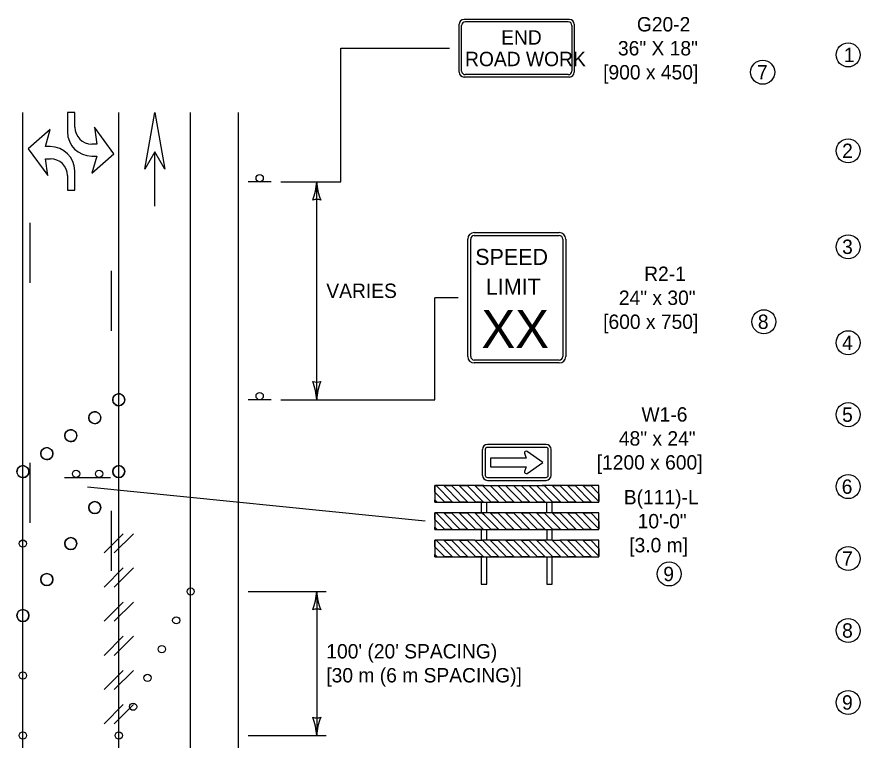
# Model space of a CAD drawing. Extents: x 49991.4 to 50021, y 49987.6 to 50011.4.
# Drawn here: x 50002.173 to 50005.691, y 50006.157 to 50009.172 of the extents above; entities that cross this region are included whole.
import ezdxf

# ---------------------------------------------------------------- set-up
doc = ezdxf.new("R2010")
doc.units = 0
for name, color, linetype in [('Level 1', 7, 'Continuous'), ('Level 2', 7, 'Continuous'), ('Level 3', 7, 'Continuous')]:
    doc.layers.add(name, color=color, linetype=linetype)

msp = doc.modelspace()

# ---------------------------------------------------------------- linework, layer by layer
at = {"layer": 'Level 1'}
for p, q in [((50004.4785, 50009.1613), (50004.0385, 50009.1613)), ((50004.0185, 50008.9413), (50004.0185, 50009.1413)), ((50004.0285, 50008.9463), (50004.0285, 50009.1363)), ((50004.4735, 50009.1513), (50004.0435, 50009.1513)), ((50004.4885, 50009.1363), (50004.4885, 50008.9463)), ((50004.4985, 50009.1413), (50004.4985, 50008.9413)), ((50004.4784, 50008.9212), (50004.0384, 50008.9212)), ((50004.4735, 50008.9313), (50004.0435, 50008.9313)), ((50002.1979, 50000.4631), (50002.1979, 50008.7736)), ((50002.4144, 50008.7735), (50002.3838, 50008.7735)), ((50002.3838, 50008.7735), (50002.3838, 50008.6926)), ((50002.4144, 50008.7128), (50002.4144, 50008.7735)), ((50002.5979, 50000.4631), (50002.5979, 50008.7736)), ((50002.8979, 50000.4631), (50002.8979, 50008.7736)), ((50003.0979, 50000.4631), (50003.0979, 50008.7736)), ((50002.3123, 50008.7022), (50002.2205, 50008.6213)), ((50002.2919, 50008.6314), (50002.3123, 50008.7022)), ((50002.5778, 50008.6017), (50002.4961, 50008.7128)), ((50002.4961, 50008.7128), (50002.5063, 50008.6421)), ((50002.3123, 50008.6314), (50002.2919, 50008.6314)), ((50002.4798, 50008.6471), (50002.4798, 50008.6471)), ((50002.5063, 50008.6421), (50002.4859, 50008.6421)), ((50002.2205, 50008.6213), (50002.3021, 50008.5101)), ((50002.4859, 50008.5208), (50002.5778, 50008.6017)), ((50002.4859, 50008.5916), (50002.5063, 50008.5916)), ((50002.5063, 50008.5916), (50002.4859, 50008.5208)), ((50002.7479, 50008.3835), (50002.7479, 50008.6094)), ((50002.7483, 50008.3835), (50002.7483, 50008.6094)), ((50002.3021, 50008.5101), (50002.2919, 50008.5809)), ((50002.2919, 50008.5809), (50002.3123, 50008.5809)), ((50002.3184, 50008.5758), (50002.3184, 50008.5758)), ((50002.4144, 50008.4495), (50002.4144, 50008.5304)), ((50002.3838, 50008.5101), (50002.3838, 50008.4495)), ((50003.2339, 50008.4843), (50003.1379, 50008.4843)), ((50002.3838, 50008.4495), (50002.4144, 50008.4495)), ((50002.2279, 50008.0631), (50002.2279, 50008.3131)), ((50004.0811, 50008.2729), (50004.4356, 50008.2729)), ((50004.0539, 50007.7562), (50004.0539, 50008.2458)), ((50004.0663, 50007.7562), (50004.0663, 50008.2458)), ((50004.0811, 50008.2605), (50004.4356, 50008.2605)), ((50004.2583, 50008.2711), (50004.2583, 50008.2711)), ((50004.4504, 50008.2458), (50004.4504, 50007.7562)), ((50004.4628, 50008.2458), (50004.4628, 50007.7562)), ((50002.5679, 50007.8631), (50002.5679, 50008.1131)), ((50004.4356, 50007.7414), (50004.0811, 50007.7414)), ((50004.4356, 50007.729), (50004.0811, 50007.729)), ((50003.2339, 50007.576), (50003.1379, 50007.576)), ((50004.1148, 50007.3687), (50004.1148, 50007.2604)), ((50004.1272, 50007.3687), (50004.1272, 50007.2604)), ((50004.3809, 50007.3897), (50004.1358, 50007.3897)), ((50004.3809, 50007.3773), (50004.1358, 50007.3773)), ((50004.3678, 50007.3146), (50004.3014, 50007.3603)), ((50004.3894, 50007.2604), (50004.3894, 50007.3687)), ((50004.4018, 50007.2604), (50004.4018, 50007.3687)), ((50004.287, 50007.3328), (50004.1488, 50007.3328)), ((50004.1488, 50007.3328), (50004.1488, 50007.2963)), ((50004.2972, 50007.3328), (50004.287, 50007.3328)), ((50004.2908, 50007.3524), (50004.2972, 50007.3328)), ((50002.2279, 50007.0631), (50002.2279, 50007.3131)), ((50004.1488, 50007.2963), (50004.2972, 50007.2963)), ((50004.2972, 50007.2963), (50004.2908, 50007.2767)), ((50004.3014, 50007.2688), (50004.3678, 50007.3146)), ((50004.1358, 50007.2519), (50004.3809, 50007.2519)), ((50002.3718, 50007.2514), (50002.4678, 50007.2514)), ((50002.4678, 50007.2514), (50002.5638, 50007.2514)), ((50003.9903, 50007.1493), (50003.9219, 50007.2177)), ((50003.9219, 50007.2177), (50003.9903, 50007.1493)), ((50004.0226, 50007.1493), (50003.9542, 50007.2177)), ((50004.0226, 50007.1493), (50003.9542, 50007.2177)), ((50004.0548, 50007.1493), (50003.9864, 50007.2177)), ((50003.9864, 50007.2177), (50004.0548, 50007.1493)), ((50004.087, 50007.1493), (50004.0186, 50007.2177)), ((50004.087, 50007.1493), (50004.0186, 50007.2177)), ((50004.1193, 50007.1493), (50004.0509, 50007.2177)), ((50004.0509, 50007.2177), (50004.1193, 50007.1493)), ((50004.1516, 50007.1493), (50004.0832, 50007.2177)), ((50004.1838, 50007.1493), (50004.1154, 50007.2177)), ((50004.1154, 50007.2177), (50004.1553, 50007.2177)), ((50004.1358, 50007.2395), (50004.3809, 50007.2395)), ((50004.1358, 50007.2177), (50004.3809, 50007.2177)), ((50004.216, 50007.1493), (50004.1476, 50007.2177)), ((50004.2482, 50007.1493), (50004.1798, 50007.2177)), ((50004.2804, 50007.1493), (50004.212, 50007.2177)), ((50004.3126, 50007.1493), (50004.2442, 50007.2177)), ((50004.3448, 50007.1493), (50004.2764, 50007.2177)), ((50004.377, 50007.1493), (50004.3086, 50007.2177)), ((50004.4094, 50007.1493), (50004.341, 50007.2177)), ((50004.3951, 50007.2177), (50004.3638, 50007.2177)), ((50004.4417, 50007.1493), (50004.3733, 50007.2177)), ((50004.474, 50007.1493), (50004.4056, 50007.2177)), ((50004.474, 50007.1493), (50004.4056, 50007.2177)), ((50004.5062, 50007.1493), (50004.4378, 50007.2177)), ((50004.4378, 50007.2177), (50004.5062, 50007.1493)), ((50004.5384, 50007.1493), (50004.47, 50007.2177)), ((50004.5384, 50007.1493), (50004.47, 50007.2177)), ((50004.5706, 50007.1493), (50004.5022, 50007.2177)), ((50004.5022, 50007.2177), (50004.5706, 50007.1493)), ((50004.6003, 50007.1518), (50004.5345, 50007.2177)), ((50004.6003, 50007.1518), (50004.5345, 50007.2177)), ((50004.6003, 50007.1841), (50004.5668, 50007.2177)), ((50004.5668, 50007.2177), (50004.6003, 50007.1841)), ((50003.9581, 50007.1493), (50003.9163, 50007.191)), ((50003.9581, 50007.1493), (50003.9163, 50007.191)), ((50003.9259, 50007.1493), (50003.9163, 50007.1588)), ((50003.9163, 50007.1588), (50003.9259, 50007.1493)), ((50004.1329, 50007.1037), (50004.1329, 50007.1493)), ((50004.3837, 50007.1037), (50004.3837, 50007.1493)), ((50002.5679, 50006.8631), (50002.5679, 50007.1131)), ((50003.9581, 50007.0353), (50003.9163, 50007.077)), ((50003.9581, 50007.0353), (50003.9163, 50007.077)), ((50003.9903, 50007.0353), (50003.9219, 50007.1037)), ((50003.9219, 50007.1037), (50003.9903, 50007.0353)), ((50004.0226, 50007.0353), (50003.9542, 50007.1037)), ((50004.0226, 50007.0353), (50003.9542, 50007.1037)), ((50004.0548, 50007.0353), (50003.9864, 50007.1037)), ((50003.9864, 50007.1037), (50004.0548, 50007.0353)), ((50004.087, 50007.0353), (50004.0186, 50007.1037)), ((50004.087, 50007.0353), (50004.0186, 50007.1037)), ((50004.1193, 50007.0353), (50004.0509, 50007.1037)), ((50004.0509, 50007.1037), (50004.1193, 50007.0353)), ((50004.1215, 50007.0653), (50004.0832, 50007.1037)), ((50004.1215, 50007.0976), (50004.1154, 50007.1037)), ((50004.1838, 50007.0353), (50004.1215, 50007.0976)), ((50004.216, 50007.0353), (50004.1476, 50007.1037)), ((50004.2482, 50007.0353), (50004.1798, 50007.1037)), ((50004.2805, 50007.0353), (50004.2121, 50007.1037)), ((50004.3128, 50007.0353), (50004.2444, 50007.1037)), ((50004.345, 50007.0353), (50004.2766, 50007.1037)), ((50004.3772, 50007.0353), (50004.3088, 50007.1037)), ((50004.4094, 50007.0353), (50004.341, 50007.1037)), ((50004.4417, 50007.0353), (50004.3733, 50007.1037)), ((50004.474, 50007.0353), (50004.4056, 50007.1037)), ((50004.474, 50007.0353), (50004.4056, 50007.1037)), ((50004.5062, 50007.0353), (50004.4378, 50007.1037)), ((50004.4378, 50007.1037), (50004.5062, 50007.0353)), ((50004.5384, 50007.0353), (50004.47, 50007.1037)), ((50004.5384, 50007.0353), (50004.47, 50007.1037)), ((50004.5706, 50007.0353), (50004.5022, 50007.1037)), ((50004.5022, 50007.1037), (50004.5706, 50007.0353)), ((50004.6003, 50007.0379), (50004.5345, 50007.1037)), ((50004.6003, 50007.0379), (50004.5345, 50007.1037)), ((50004.6003, 50007.0701), (50004.5668, 50007.1037)), ((50004.5668, 50007.1037), (50004.6003, 50007.0701)), ((50003.9259, 50007.0353), (50003.9163, 50007.0448)), ((50003.9163, 50007.0448), (50003.9259, 50007.0353)), ((50004.1516, 50007.0353), (50004.1215, 50007.0653)), ((50002.5366, 50006.937), (50002.6166, 50007.017)), ((50002.5791, 50006.937), (50002.6591, 50007.017)), ((50003.9903, 50006.9214), (50003.9219, 50006.9898)), ((50003.9219, 50006.9898), (50003.9903, 50006.9214)), ((50004.0226, 50006.9214), (50003.9542, 50006.9898)), ((50004.0226, 50006.9214), (50003.9542, 50006.9898)), ((50004.0548, 50006.9214), (50003.9864, 50006.9898)), ((50003.9864, 50006.9898), (50004.0548, 50006.9214)), ((50004.087, 50006.9214), (50004.0186, 50006.9898)), ((50004.087, 50006.9214), (50004.0186, 50006.9898)), ((50004.1193, 50006.9214), (50004.0509, 50006.9898)), ((50004.0509, 50006.9898), (50004.1193, 50006.9214)), ((50004.1516, 50006.9214), (50004.0832, 50006.9898)), ((50004.1516, 50006.9214), (50004.0832, 50006.9898)), ((50004.1838, 50006.9214), (50004.1154, 50006.9898)), ((50004.1154, 50006.9898), (50004.1838, 50006.9214)), ((50004.216, 50006.9214), (50004.1476, 50006.9898)), ((50004.216, 50006.9214), (50004.1476, 50006.9898)), ((50004.2482, 50006.9214), (50004.1798, 50006.9898)), ((50004.1798, 50006.9898), (50004.2482, 50006.9214)), ((50004.2805, 50006.9214), (50004.2121, 50006.9898)), ((50004.2805, 50006.9214), (50004.2121, 50006.9898)), ((50004.3128, 50006.9214), (50004.2444, 50006.9898)), ((50004.2444, 50006.9898), (50004.3128, 50006.9214)), ((50004.345, 50006.9214), (50004.2766, 50006.9898)), ((50004.345, 50006.9214), (50004.2766, 50006.9898)), ((50004.3772, 50006.9214), (50004.3088, 50006.9898)), ((50004.3088, 50006.9898), (50004.3772, 50006.9214)), ((50004.4094, 50006.9214), (50004.341, 50006.9898)), ((50004.4094, 50006.9214), (50004.341, 50006.9898)), ((50004.4417, 50006.9214), (50004.3733, 50006.9898)), ((50004.3733, 50006.9898), (50004.4417, 50006.9214)), ((50004.474, 50006.9214), (50004.4056, 50006.9898)), ((50004.474, 50006.9214), (50004.4056, 50006.9898)), ((50004.5062, 50006.9214), (50004.4378, 50006.9898)), ((50004.4378, 50006.9898), (50004.5062, 50006.9214)), ((50004.5384, 50006.9214), (50004.47, 50006.9898)), ((50004.5384, 50006.9214), (50004.47, 50006.9898)), ((50004.5706, 50006.9214), (50004.5022, 50006.9898)), ((50004.5022, 50006.9898), (50004.5706, 50006.9214)), ((50004.6003, 50006.9239), (50004.5345, 50006.9898)), ((50004.6003, 50006.9239), (50004.5345, 50006.9898)), ((50004.6003, 50006.9561), (50004.5668, 50006.9898)), ((50004.5668, 50006.9898), (50004.6003, 50006.9561)), ((50003.9581, 50006.9214), (50003.9163, 50006.9631)), ((50003.9581, 50006.9214), (50003.9163, 50006.9631)), ((50003.9259, 50006.9214), (50003.9163, 50006.9309)), ((50003.9163, 50006.9309), (50003.9259, 50006.9214)), ((50002.5366, 50006.7946), (50002.6166, 50006.8746)), ((50002.5791, 50006.7946), (50002.6591, 50006.8746)), ((50002.5366, 50006.6522), (50002.6166, 50006.7322)), ((50002.5791, 50006.6522), (50002.6591, 50006.7322)), ((50002.5366, 50006.5098), (50002.6166, 50006.5898)), ((50002.5791, 50006.5098), (50002.6591, 50006.5898)), ((50002.5366, 50006.3673), (50002.6166, 50006.4473)), ((50002.5791, 50006.3673), (50002.6591, 50006.4473)), ((50002.5366, 50006.2249), (50002.6166, 50006.3049)), ((50002.5791, 50006.2249), (50002.6591, 50006.3049))]:
    msp.add_line(p, q, dxfattribs=at)
msp.add_lwpolyline([(50002.7063, 50008.5371), (50002.7479, 50008.7736), (50002.7899, 50008.5371), (50002.7479, 50008.6093)], close=True, dxfattribs=at)
for points in [[(50004.1215, 50007.2177), (50003.9163, 50007.2177), (50003.9163, 50007.1493), (50004.1215, 50007.1493)], [(50003.9163, 50007.191), (50003.9163, 50007.2177), (50003.9219, 50007.2177)], [(50003.9542, 50007.2177), (50003.9864, 50007.2177)], [(50004.0186, 50007.2177), (50004.0509, 50007.2177)], [(50004.1838, 50007.1493), (50004.1516, 50007.1493), (50004.0832, 50007.2177), (50004.1154, 50007.2177), (50004.1838, 50007.1493)], [(50004.1215, 50007.1493), (50004.6003, 50007.1493), (50004.6003, 50007.2177), (50004.3951, 50007.2177)], [(50004.1476, 50007.2177), (50004.1553, 50007.2177), (50004.1798, 50007.2177), (50004.2482, 50007.1493), (50004.216, 50007.1493), (50004.1476, 50007.2177)], [(50004.212, 50007.2177), (50004.2442, 50007.2177), (50004.3126, 50007.1493), (50004.2804, 50007.1493), (50004.212, 50007.2177)], [(50004.2764, 50007.2177), (50004.3086, 50007.2177), (50004.377, 50007.1493), (50004.3448, 50007.1493), (50004.2764, 50007.2177)], [(50004.341, 50007.2177), (50004.3638, 50007.2177), (50004.3733, 50007.2177), (50004.4417, 50007.1493), (50004.4094, 50007.1493), (50004.341, 50007.2177)], [(50004.4056, 50007.2177), (50004.4378, 50007.2177)], [(50004.47, 50007.2177), (50004.5022, 50007.2177)], [(50004.5345, 50007.2177), (50004.5668, 50007.2177)], [(50004.6003, 50007.1841), (50004.6003, 50007.1518)], [(50003.9259, 50007.1493), (50003.9163, 50007.1493), (50003.9163, 50007.1588)], [(50003.9903, 50007.1493), (50003.9581, 50007.1493)], [(50004.0548, 50007.1493), (50004.0226, 50007.1493)], [(50004.1193, 50007.1493), (50004.087, 50007.1493)], [(50004.1101, 50007.1493), (50004.1101, 50007.1037)], [(50004.4065, 50007.1037), (50004.4065, 50007.1493)], [(50004.5062, 50007.1493), (50004.474, 50007.1493)], [(50004.5706, 50007.1493), (50004.5384, 50007.1493)], [(50004.1215, 50007.1037), (50003.9163, 50007.1037), (50003.9163, 50007.0353), (50004.6003, 50007.0353), (50004.6003, 50007.1037), (50004.1215, 50007.1037)], [(50003.9163, 50007.077), (50003.9163, 50007.1037), (50003.9219, 50007.1037)], [(50003.9542, 50007.1037), (50003.9864, 50007.1037)], [(50004.0186, 50007.1037), (50004.0509, 50007.1037)], [(50004.1838, 50007.0353), (50004.1516, 50007.0353), (50004.1215, 50007.0653), (50004.0832, 50007.1037), (50004.1101, 50007.1037), (50004.1154, 50007.1037), (50004.1215, 50007.0976), (50004.1838, 50007.0353)], [(50004.1476, 50007.1037), (50004.1798, 50007.1037), (50004.2482, 50007.0353), (50004.216, 50007.0353), (50004.1476, 50007.1037)], [(50004.2121, 50007.1037), (50004.2444, 50007.1037), (50004.3128, 50007.0353), (50004.2805, 50007.0353), (50004.2121, 50007.1037)], [(50004.2766, 50007.1037), (50004.3088, 50007.1037), (50004.3772, 50007.0353), (50004.345, 50007.0353), (50004.2766, 50007.1037)], [(50004.341, 50007.1037), (50004.3733, 50007.1037), (50004.4417, 50007.0353), (50004.4094, 50007.0353), (50004.341, 50007.1037)], [(50004.4056, 50007.1037), (50004.4378, 50007.1037)], [(50004.47, 50007.1037), (50004.5022, 50007.1037)], [(50004.5345, 50007.1037), (50004.5668, 50007.1037)], [(50003.9259, 50007.0353), (50003.9163, 50007.0353), (50003.9163, 50007.0448)], [(50004.6003, 50007.0701), (50004.6003, 50007.0379)], [(50003.9903, 50007.0353), (50003.9581, 50007.0353)], [(50004.0548, 50007.0353), (50004.0226, 50007.0353)], [(50004.1193, 50007.0353), (50004.087, 50007.0353)], [(50004.1101, 50007.0353), (50004.1101, 50006.9898)], [(50004.1329, 50006.9898), (50004.1329, 50007.0353)], [(50004.3837, 50007.0353), (50004.3837, 50006.9898)], [(50004.4065, 50006.9898), (50004.4065, 50007.0353)], [(50004.5062, 50007.0353), (50004.474, 50007.0353)], [(50004.5706, 50007.0353), (50004.5384, 50007.0353)], [(50003.9163, 50006.9631), (50003.9163, 50006.9898), (50003.9219, 50006.9898)], [(50004.0832, 50006.9898), (50003.9163, 50006.9898), (50003.9163, 50006.9214), (50004.6003, 50006.9214), (50004.6003, 50006.9898), (50004.4378, 50006.9898)], [(50003.9542, 50006.9898), (50003.9864, 50006.9898)], [(50004.0186, 50006.9898), (50004.0509, 50006.9898)], [(50004.0832, 50006.9898), (50004.1154, 50006.9898)], [(50004.4056, 50006.9898), (50004.1154, 50006.9898)], [(50004.1476, 50006.9898), (50004.1798, 50006.9898)], [(50004.2121, 50006.9898), (50004.2444, 50006.9898)], [(50004.2766, 50006.9898), (50004.3088, 50006.9898)], [(50004.341, 50006.9898), (50004.3733, 50006.9898)], [(50004.4056, 50006.9898), (50004.4378, 50006.9898)], [(50004.47, 50006.9898), (50004.5022, 50006.9898)], [(50004.5345, 50006.9898), (50004.5668, 50006.9898)], [(50004.6003, 50006.9561), (50004.6003, 50006.9239)], [(50003.9259, 50006.9214), (50003.9163, 50006.9214), (50003.9163, 50006.9309)], [(50003.9903, 50006.9214), (50003.9581, 50006.9214)], [(50004.0548, 50006.9214), (50004.0226, 50006.9214)], [(50004.1193, 50006.9214), (50004.087, 50006.9214)], [(50004.1101, 50006.9213), (50004.1101, 50006.8073), (50004.1329, 50006.8073), (50004.1329, 50006.9213)], [(50004.1838, 50006.9214), (50004.1516, 50006.9214)], [(50004.2482, 50006.9214), (50004.216, 50006.9214)], [(50004.3128, 50006.9214), (50004.2805, 50006.9214)], [(50004.3772, 50006.9214), (50004.345, 50006.9214)], [(50004.3837, 50006.9213), (50004.3837, 50006.8073), (50004.4065, 50006.8073), (50004.4065, 50006.9213)], [(50004.4417, 50006.9214), (50004.4094, 50006.9214)], [(50004.5062, 50006.9214), (50004.474, 50006.9214)], [(50004.5706, 50006.9214), (50004.5384, 50006.9214)]]:
    msp.add_lwpolyline(points, dxfattribs=at)
for centre, radius in [((50003.1858, 50008.4994), 0.0152), ((50003.1858, 50007.5911), 0.0152), ((50002.5979, 50007.576), 0.025), ((50002.4979, 50007.501), 0.025), ((50002.3979, 50007.426), 0.025), ((50002.2979, 50007.351), 0.025), ((50002.1979, 50007.276), 0.025), ((50002.5979, 50007.276), 0.025), ((50002.4198, 50007.2666), 0.0152), ((50002.5158, 50007.2666), 0.0152), ((50002.4979, 50007.126), 0.025), ((50002.1979, 50006.976), 0.015), ((50002.3979, 50006.976), 0.025), ((50002.2979, 50006.826), 0.025), ((50002.8979, 50006.776), 0.015), ((50002.1979, 50006.676), 0.025), ((50002.8378, 50006.656), 0.015), ((50002.7778, 50006.5359), 0.015), ((50002.1979, 50006.426), 0.015), ((50002.7178, 50006.4159), 0.015), ((50002.6578, 50006.2959), 0.015), ((50002.1979, 50006.176), 0.015), ((50002.5979, 50006.176), 0.015)]:
    msp.add_circle(centre, radius, dxfattribs=at)
for centre, radius, start, end in [((50004.0385, 50009.1413), 0.02, 90, 180), ((50004.4785, 50009.1413), 0.02, 360, 90), ((50004.0435, 50009.1363), 0.015, 90, 180), ((50004.4735, 50009.1363), 0.015, 360, 90), ((50004.0384, 50008.9413), 0.02, 180, 270), ((50004.0435, 50008.9463), 0.015, 180, 270), ((50004.4735, 50008.9463), 0.015, 270, 360), ((50004.4784, 50008.9413), 0.02, 270, 360), ((50004.0811, 50008.2458), 0.0272, 90, 180), ((50004.4356, 50008.2458), 0.0272, 0, 90), ((50004.0811, 50008.2458), 0.0148, 90, 180), ((50004.4356, 50008.2458), 0.0148, 0, 90), ((50004.0811, 50007.7562), 0.0272, 180, 270), ((50004.0811, 50007.7562), 0.0148, 180, 270), ((50004.4356, 50007.7562), 0.0148, 270, 360), ((50004.4356, 50007.7562), 0.0272, 270, 360), ((50002.5979, 50007.576), 0.025, 10.3048, 190.3048), ((50002.5979, 50007.576), 0.025, 190.3048, 10.3048), ((50002.4979, 50007.501), 0.025, 10.3048, 190.3048), ((50002.4979, 50007.501), 0.025, 190.3048, 10.3048), ((50002.3979, 50007.426), 0.025, 10.3048, 190.3048), ((50002.3979, 50007.426), 0.025, 190.3048, 10.3048), ((50002.2979, 50007.351), 0.025, 10.3048, 190.3048), ((50004.1358, 50007.3687), 0.0209, 90, 180), ((50004.1358, 50007.3687), 0.00855, 90, 180), ((50004.2974, 50007.3545), 0.00695, 55.4806, 197.9582), ((50004.3809, 50007.3687), 0.0209, 0, 90), ((50004.3809, 50007.3687), 0.00855, 0, 90), ((50002.2979, 50007.351), 0.025, 190.3048, 10.3048), ((50002.1979, 50007.276), 0.025, 10.3048, 190.3048), ((50002.5979, 50007.276), 0.025, 0, 180), ((50002.1979, 50007.276), 0.025, 190.3048, 10.3048), ((50002.5979, 50007.276), 0.025, 180, 0), ((50004.1358, 50007.2604), 0.0209, 180, 270), ((50004.1358, 50007.2604), 0.00855, 180, 270), ((50004.2974, 50007.2746), 0.00695, 162.0418, 304.5194), ((50004.3809, 50007.2604), 0.00855, 270, 360), ((50004.3809, 50007.2604), 0.0209, 270, 360), ((50002.4979, 50007.126), 0.025, 0, 180), ((50002.4979, 50007.126), 0.025, 180, 0), ((50002.3979, 50006.976), 0.025, 0, 180), ((50002.3979, 50006.976), 0.025, 180, 0), ((50002.2979, 50006.826), 0.025, 0, 180), ((50002.2979, 50006.826), 0.025, 180, 0), ((50002.1979, 50006.676), 0.025, 0, 180), ((50002.1979, 50006.676), 0.025, 180, 0)]:
    msp.add_arc(centre, radius, start, end, dxfattribs=at)
for centre, major_axis in [((50002.4859, 50008.7128), (-0.0715, 0)), ((50002.4859, 50008.6926), (-0.1021, 0)), ((50002.3123, 50008.5303), (0.1021, 0)), ((50002.3123, 50008.5101), (0.0715, 0))]:
    msp.add_ellipse(centre, major_axis=major_axis, ratio=0.990099, start_param=0, end_param=1.570796, dxfattribs=at)
at = {"layer": 'Level 2'}
for centre in [(50005.6409, 50009.0136), (50005.2844, 50008.9413), (50005.6409, 50008.6136), (50005.6409, 50008.2136), (50005.2893, 50007.901), (50005.6409, 50007.8136), (50005.6409, 50007.5136), (50005.6409, 50007.2136), (50005.6409, 50006.9136), (50004.8943, 50006.8494), (50005.6409, 50006.6136), (50005.6409, 50006.3136)]:
    msp.add_circle(centre, 0.0501, dxfattribs=at)
at = {"layer": 'Level 3'}
for p, q in [((50003.2739, 50008.4843), (50003.5239, 50008.4843)), ((50003.4239, 50007.576), (50003.4239, 50008.4843)), ((50003.9162, 50007.576), (50003.9162, 50008.001)), ((50004.0139, 50008.001), (50003.9162, 50008.001)), ((50003.2739, 50007.576), (50003.9162, 50007.576)), ((50003.8763, 50007.0695), (50002.4678, 50007.2114)), ((50003.1379, 50006.776), (50003.4639, 50006.776)), ((50003.4239, 50006.776), (50003.4239, 50006.176)), ((50003.1379, 50006.176), (50003.4639, 50006.176))]:
    msp.add_line(p, q, dxfattribs=at)
msp.add_lwpolyline([(50003.5239, 50008.4843), (50003.5239, 50009.0413), (50003.9785, 50009.0413)], dxfattribs=at)
for centre, radius, start, end in [((50003.2017, 50008.4934), 0.2223, 337.456, 357.6395), ((50003.6566, 50008.4958), 0.233, 182.8273, 202.0772), ((50003.4239, 50008.3561), 0.0548, 72.1388, 107.8612), ((50003.4239, 50007.7042), 0.0548, 252.1388, 287.8612), ((50003.1911, 50007.5645), 0.233, 2.8273, 22.0772), ((50003.646, 50007.5668), 0.2223, 157.456, 177.6395), ((50003.2017, 50006.7852), 0.2223, 337.456, 357.6395), ((50003.6566, 50006.7875), 0.233, 182.8273, 202.0772), ((50003.4239, 50006.6478), 0.0548, 72.1388, 107.8612), ((50003.4239, 50006.3042), 0.0548, 252.1388, 287.8612), ((50003.1911, 50006.1645), 0.233, 2.8273, 22.0772), ((50003.646, 50006.1668), 0.2223, 157.456, 177.6395)]:
    msp.add_arc(centre, radius, start, end, dxfattribs=at)

# ---------------------------------------------------------------- texts
at = {"layer": 'Level 1'}
for s, p in [('END', (50004.1933, 50009.0566)), ('ROAD WORK', (50004.0427, 50008.9666))]:
    msp.add_text(s, height=0.06, rotation=360, dxfattribs=at).set_placement(p)
for s, height, p in [('SPEED', 0.06696, (50004.0852, 50008.1378)), ('LIMIT', 0.06696, (50004.1295, 50008.014)), ('XX', 0.15775, (50004.1112, 50007.792))]:
    msp.add_text(s, height=height, dxfattribs=at).set_placement(p)
at = {"layer": 'Level 2'}
for s, height, p in [('G20-2', 0.06, (50004.7596, 50009.1113)), ('36" X 18"', 0.06, (50004.6806, 50009.0113)), ('1', 0.06, (50005.6231, 50008.9836)), ('[900 x 450]', 0.06, (50004.6188, 50008.9113)), ('7', 0.0601, (50005.2606, 50008.9112)), ('2', 0.06, (50005.6158, 50008.5836)), ('3', 0.06, (50005.6158, 50008.1836)), ('R2-1', 0.06, (50004.7899, 50008.071)), ('24" x 30"', 0.06, (50004.6844, 50007.971)), ('[600 x 750]', 0.06, (50004.6188, 50007.871)), ('8', 0.06, (50005.2643, 50007.871)), ('4', 0.06, (50005.6158, 50007.7836)), ('W1-6', 0.06, (50004.7788, 50007.4846)), ('5', 0.06, (50005.6157, 50007.4836)), ('48" x 24"', 0.06, (50004.6844, 50007.3846)), ('[1200 x 600]', 0.06, (50004.5919, 50007.2846)), ('6', 0.06, (50005.6141, 50007.1836)), ('B(111)-L', 0.06, (50004.705, 50007.1395)), ('10\'-0"', 0.06, (50004.7628, 50007.0395)), ('[3.0 m]', 0.06, (50004.7276, 50006.9395)), ('7', 0.06, (50005.6158, 50006.8836)), ('9', 0.06, (50004.8698, 50006.8194)), ('8', 0.06, (50005.6158, 50006.5836)), ("100' (20' SPACING)", 0.06, (50003.4639, 50006.497)), ('[30 m (6 m SPACING)]', 0.06, (50003.4639, 50006.397)), ('9', 0.06, (50005.6155, 50006.2836))]:
    msp.add_text(s, height=height, dxfattribs=at).set_placement(p)
msp.add_text('VARIES', height=0.06, rotation=360, dxfattribs=at).set_placement((50003.4639, 50008.0001))

doc.saveas('drawing.dxf')
